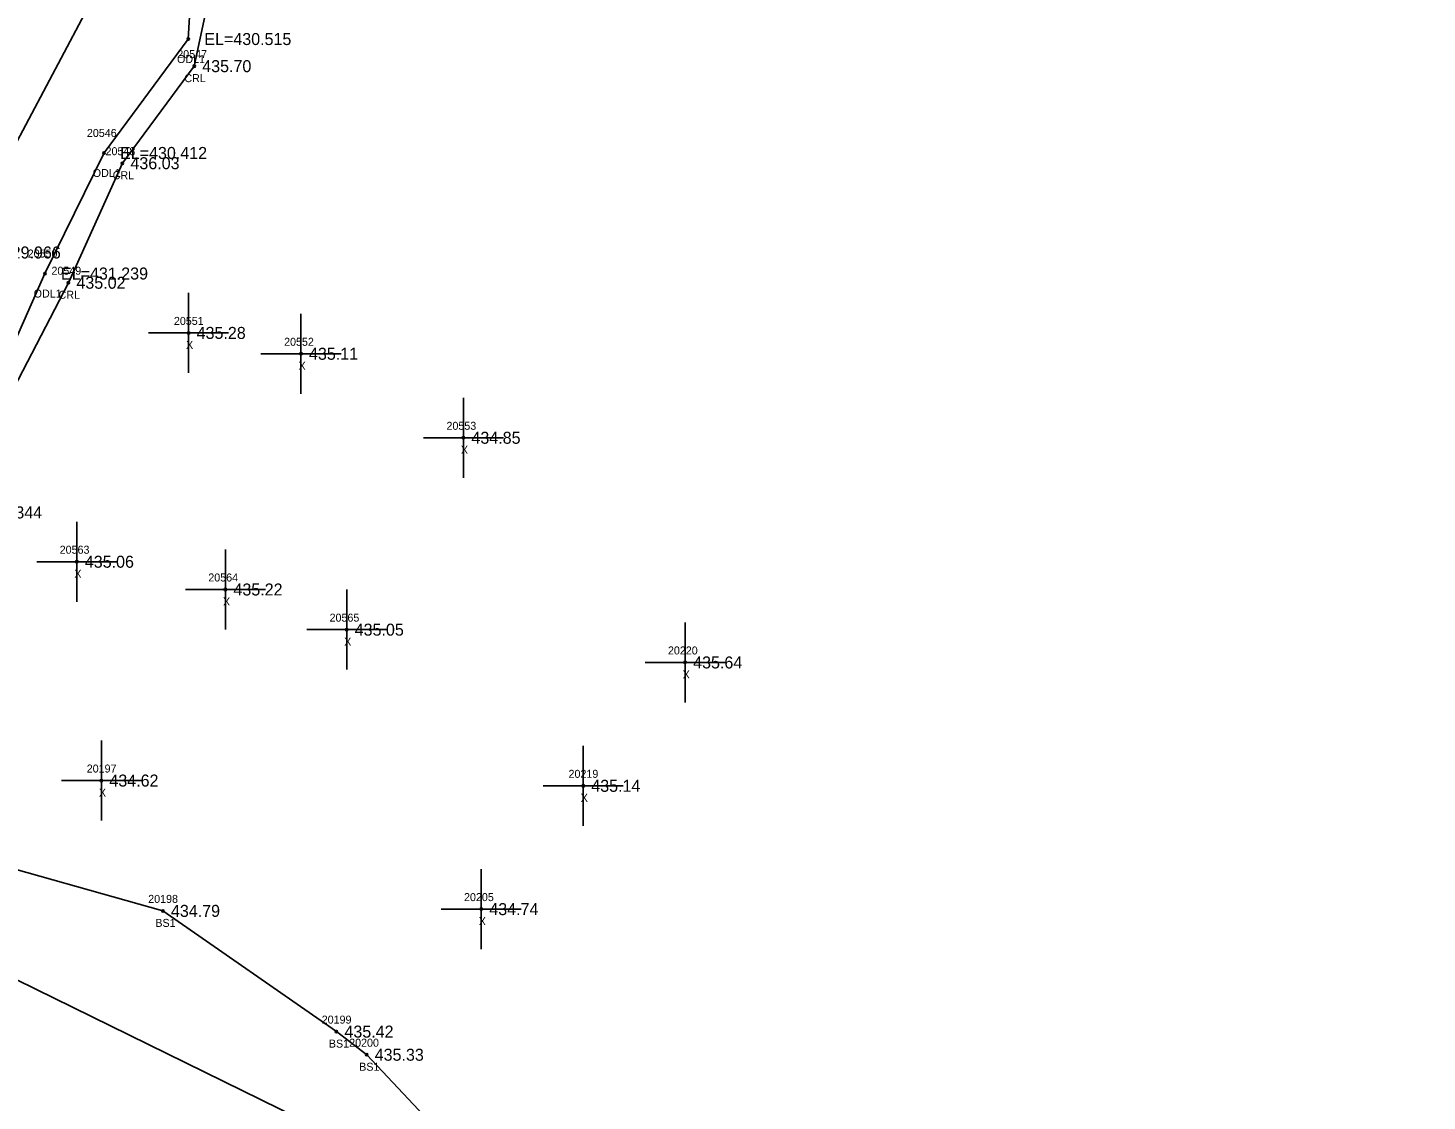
# Model space of a CAD drawing. Extents: x 1613836 to 1615109, y 777151 to 778248.
# Drawn here: x 1614505.3 to 1614680.1, y 777672.3 to 777806.4 of the extents above; entities that cross this region are included whole.
import ezdxf

# ---------------------------------------------------------------- set-up
doc = ezdxf.new("R2010")
doc.units = 0
for name, color, linetype in [('RD_DTM_BkLn2', 7, 'Continuous'), ('RD_DTM_BkLn_txCode', 7, 'Continuous'), ('RD_EX_H2O', 7, 'Continuous'), ('RD_EX_H2O_txCode', 7, 'Continuous'), ('RD_EX_Misc', 7, 'Continuous'), ('RD_EX_Misc_txCode', 7, 'Continuous'), ('RD_EX_TX_H2O_ELEV', 7, 'Continuous'), ('RD_EX_TX_Misc_ELEV', 7, 'Continuous'), ('RD_SMD_Locator', 7, 'Continuous')]:
    doc.layers.add(name, color=color, linetype=linetype)

msp = doc.modelspace()

# ---------------------------------------------------------------- linework, layer by layer
at = {"layer": 'RD_DTM_BkLn2'}
for points in [[(1614480.98, 777699.79), (1614497.59, 777703), (1614522.19, 777696.07), (1614543.87, 777680.98), (1614547.65, 777678.09), (1614587.23, 777635.96), (1614610.74, 777599.44), (1614633.11, 777578.17), (1614686.46, 777534.25), (1614763.32, 777471.34), (1614841.29, 777408.4), (1614909.19, 777352.07)], [(1614487.8, 777694.98), (1614492.09, 777693.24), (1614539.12, 777670.15), (1614581.25, 777629.02), (1614608.07, 777595.47), (1614631.79, 777576.16), (1614684.94, 777532.19), (1614761.79, 777469.29), (1614840.42, 777406.78), (1614908.46, 777350.38), (1614912.05, 777350.16), (1614911.85, 777355.47)]]:
    msp.add_lwpolyline(points, dxfattribs=at)
at = {"layer": 'RD_EX_H2O'}
for points in [[(1614639.54, 778230.63), (1614634.52, 778174.88), (1614617.02, 778127.08), (1614609.96, 778108.29), (1614618.6, 778090.08), (1614618.65, 778056.48), (1614610.43, 778030), (1614589.62, 777977.97), (1614569.81, 777927.89), (1614565.63, 777909.32), (1614534.03, 777865.55), (1614528.13, 777847.05), (1614516.47, 777815.91), (1614496.55, 777778.36), (1614481.67, 777748.03), (1614471.7, 777724.98), (1614468.53, 777719.48), (1614464.55, 777708.61), (1614459.06, 777697.65), (1614451.34, 777685.51), (1614441.64, 777670.36)], [(1614639.33, 778020.47), (1614638.8, 778019.37), (1614635.18, 778014.85), (1614627.32, 778013.74), (1614620.1, 778009.9), (1614613.61, 778005.82), (1614608.34, 778003.27), (1614599.89, 777971.68), (1614580.65, 777921.1), (1614573.17, 777903.34), (1614544.02, 777862.61), (1614536.62, 777846.2), (1614525.93, 777814.9), (1614525.36, 777805.04), (1614514.83, 777790.8), (1614507.45, 777775.73), (1614494.22, 777745.87), (1614477.07, 777716.66), (1614470.86, 777703.72), (1614467.03, 777692.39), (1614458.98, 777681.06), (1614454.05, 777670.72)], [(1614612.84, 778001.09), (1614602.8, 777969.59), (1614583.96, 777919.69), (1614574.96, 777902.32), (1614550.82, 777861.38), (1614543.23, 777842.17), (1614528.68, 777813.75), (1614526.1, 777801.65), (1614517.13, 777789.52), (1614510.38, 777774.58), (1614495.52, 777745.97), (1614480.57, 777714.78), (1614474.46, 777705.96), (1614477.93, 777705.13), (1614481.15, 777703.4), (1614481.27, 777700.99), (1614480.97, 777699.74), (1614478.44, 777696.16), (1614475.82, 777697.62), (1614468.32, 777689.25), (1614463.06, 777676.24), (1614459.87, 777668.19)]]:
    msp.add_lwpolyline(points, dxfattribs=at)
at = {"layer": 'RD_EX_Misc'}
for p, q in [((1614525.4, 777763.31), (1614525.4, 777773.31)), ((1614539.44, 777760.7), (1614539.44, 777770.7)), ((1614520.4, 777768.31), (1614530.4, 777768.31)), ((1614534.44, 777765.7), (1614544.44, 777765.7)), ((1614559.74, 777750.2), (1614559.74, 777760.2)), ((1614554.74, 777755.2), (1614564.74, 777755.2)), ((1614511.43, 777734.71), (1614511.43, 777744.71)), ((1614530, 777731.24), (1614530, 777741.24)), ((1614506.43, 777739.71), (1614516.43, 777739.71)), ((1614525, 777736.24), (1614535, 777736.24)), ((1614545.15, 777726.22), (1614545.15, 777736.22)), ((1614587.44, 777722.12), (1614587.44, 777732.12)), ((1614540.15, 777731.22), (1614550.15, 777731.22)), ((1614582.44, 777727.12), (1614592.44, 777727.12)), ((1614514.5, 777707.36), (1614514.5, 777717.36)), ((1614574.71, 777706.7), (1614574.71, 777716.7)), ((1614509.5, 777712.36), (1614519.5, 777712.36)), ((1614569.71, 777711.7), (1614579.71, 777711.7)), ((1614561.97, 777691.29), (1614561.97, 777701.29)), ((1614556.97, 777696.29), (1614566.97, 777696.29))]:
    msp.add_line(p, q, dxfattribs=at)
at = {"layer": 'RD_SMD_Locator'}
for centre in [(1614525.36, 777805.04), (1614526.1, 777801.65), (1614514.83, 777790.8), (1614517.13, 777789.52), (1614507.45, 777775.73), (1614510.38, 777774.58), (1614525.4, 777768.31), (1614539.44, 777765.7), (1614559.74, 777755.2), (1614511.43, 777739.71), (1614530, 777736.24), (1614545.15, 777731.22), (1614587.44, 777727.12), (1614514.5, 777712.36), (1614574.71, 777711.7), (1614522.19, 777696.07), (1614561.97, 777696.29), (1614543.87, 777680.98), (1614547.65, 777678.09)]:
    msp.add_circle(centre, 0.15, dxfattribs=at)

# ---------------------------------------------------------------- texts
at = {"layer": 'RD_DTM_BkLn_txCode'}
for s, p in [('20198', (1614520.35, 777697.07)), ('BS1', (1614521.24, 777694.07)), ('20199', (1614542.03, 777681.98)), ('BS1', (1614542.92, 777678.98)), ('20200', (1614545.46, 777679.09)), ('BS1', (1614546.71, 777676.09))]:
    msp.add_text(s, height=1, dxfattribs=at).set_placement(p)
at = {"layer": 'RD_EX_H2O_txCode'}
for s, p in [('20547', (1614523.98, 777802.65)), ('ODL1', (1614523.95, 777802.04)), ('CRL', (1614524.87, 777799.65)), ('20546', (1614512.69, 777792.8)), ('20548', (1614515.02, 777790.52)), ('ODL1', (1614513.42, 777787.8)), ('CRL', (1614515.91, 777787.52)), ('20550', (1614505.29, 777777.73)), ('20549', (1614508.26, 777775.58)), ('ODL1', (1614506.04, 777772.73)), ('CRL', (1614509.15, 777772.58))]:
    msp.add_text(s, height=1, dxfattribs=at).set_placement(p)
at = {"layer": 'RD_EX_Misc_txCode'}
for s, p in [('20551', (1614523.56, 777769.31)), ('X', (1614525.08, 777766.31)), ('20552', (1614537.33, 777766.7)), ('X', (1614539.13, 777763.7)), ('20553', (1614557.62, 777756.2)), ('X', (1614559.42, 777753.2)), ('20563', (1614509.29, 777740.71)), ('X', (1614511.12, 777737.71)), ('20564', (1614527.86, 777737.24)), ('X', (1614529.69, 777734.24)), ('20565', (1614543.01, 777732.22)), ('X', (1614544.84, 777729.22)), ('20220', (1614585.29, 777728.12)), ('X', (1614587.13, 777725.12)), ('20197', (1614512.67, 777713.36)), ('20219', (1614572.87, 777712.7)), ('X', (1614514.19, 777710.36)), ('X', (1614574.39, 777709.7)), ('20205', (1614559.81, 777697.29)), ('X', (1614561.65, 777694.29))]:
    msp.add_text(s, height=1, dxfattribs=at).set_placement(p)
at = {"layer": 'RD_EX_TX_H2O_ELEV'}
for s, p in [('EL=430.515', (1614527.36, 777804.29)), ('435.70', (1614527.1, 777800.9)), ('EL=430.412', (1614516.83, 777790.05)), ('436.03', (1614518.13, 777788.77)), ('EL=429.966', (1614498.55, 777777.61)), ('EL=431.239', (1614509.45, 777774.98)), ('435.02', (1614511.38, 777773.83)), ('EL=430.344', (1614496.22, 777745.12))]:
    msp.add_text(s, height=1.5, dxfattribs=at).set_placement(p)
at = {"layer": 'RD_EX_TX_Misc_ELEV'}
for s, p in [('435.28', (1614526.4, 777767.56)), ('435.11', (1614540.44, 777764.95)), ('434.85', (1614560.74, 777754.45)), ('435.06', (1614512.43, 777738.96)), ('435.22', (1614531, 777735.49)), ('435.05', (1614546.15, 777730.47)), ('435.64', (1614588.44, 777726.37)), ('434.62', (1614515.5, 777711.61)), ('435.14', (1614575.71, 777710.95)), ('434.74', (1614562.97, 777695.54)), ('434.79', (1614523.19, 777695.32)), ('435.42', (1614544.87, 777680.23)), ('435.33', (1614548.65, 777677.34))]:
    msp.add_text(s, height=1.5, dxfattribs=at).set_placement(p)

doc.saveas('drawing.dxf')
